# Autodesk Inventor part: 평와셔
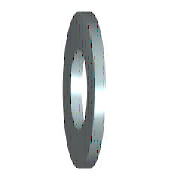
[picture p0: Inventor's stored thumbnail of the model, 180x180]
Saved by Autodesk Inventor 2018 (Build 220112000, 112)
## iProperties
IsCustomPart: 1
Created: 2012-02
Part Number: 평와셔
Material: 강철
Description: 평면 와셔 - 초대형 시리즈 - 제품 등급 C
Document SubType Name: Modeling
Standard: ISO 7094
Designer: mduedu
Standard Revision: Second edition 2000-06-01
Standards Organization: ISO
Language: ko-KR
Size Designation: ST 5 - 100 HV
Categories: <MemberInstance><Categories><Category DisplayName="조임쇠" InternalName="e4da775c-781d-43d5-af7c-5136215cf5a6" Mnemonic="FSTN"><Category DisplayName="와셔" InternalN
Density: 7.85 g/cm^3
Appearance: 강철
Mass: 3.62216 g
Surface Area: 6.09076 cm^2
Volume: 0.461421 cm^3
Author: mduedu
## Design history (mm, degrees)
sketch "스케치"
  geometry: C1 r 9 at (0, 0); C2 r 2.75 at (0, 0); 1 further point
  constraints: 2 centre point, 2 coincident
  dimensions: "d0" = 5.5 diameter of C2 (= SD1); "d1" = 18 diameter of C1 (= SD2)
extrude "본체" new body sketch "스케치" distance "d2" = 2 (= SD); taper "d3" = 0 deg
workaxis "Work Axis1"
workplane "Work Plane1"
body "Solid1"
other parameters: "SD1" = 5.5 [user parameter; used in 1 equation term], "SD2" = 18 [user parameter; used in 1 equation term], "SD" = 2 [user parameter; used in 1 equation term], "d4" = 0, "d5" = 0, "d6" = 0, "d7" = 0, "NND" = 5 [user parameter]
